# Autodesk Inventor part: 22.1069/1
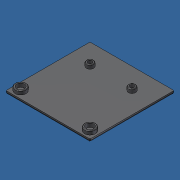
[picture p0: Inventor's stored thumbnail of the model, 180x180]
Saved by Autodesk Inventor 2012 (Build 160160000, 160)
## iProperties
Created: 2007-01
Part Number: 22.1069/1
Document SubType Name: Modeling
Designer: Andy Moles
Material: ABS Plastic
Density: 1.06 g/cm^3
Mass: 26.2439 g
Surface Area: 178.352 cm^2
Volume: 24.7584 cm^3
Description: END CAP 90X90 GRAY
Vendor: S
Author: Andy Moles
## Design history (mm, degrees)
sketch "Sketch1"
  geometry: L1 (-45, 45)-(45, 45); L2 (45, 45)-(45, -45); L3 (45, -45)-(-45, -45); L4 (-45, -45)-(-45, 45); 1 further point
  constraints: 8 end point, 2 parallel, 1 horizontal, 1 perpendicular
  dimensions: "WIDTH1" = 90 distance of L1.end L2.end; "WIDTH2" = 90 distance of L1.start L1.end; "d2" = 45 distance from line of point (0, 0) L1; "d3" = 45 distance from line of point (0, 0) L2
extrude "Extrusion1" new body sketch "Sketch1" distance "d4" = 3; taper "d5" = 0 deg
fillet "Fillet1" dims "d6" = 1
fillet "Fillet2" dims "d7" = 1.5
sketch "Sketch2"
  geometry: L1 (44, -45)-(-44, -45) reference; L2 (-44, 45)-(44, 45) reference; L3 (-45, -44)-(-45, 44) reference; C1 r 5.875 at (-37.15, -37.15); C2 r 4.25 at (-37.15, -37.15); C3 r 2.375 at (-22.5, 22.5); C4 r 3.825 at (-22.5, 22.5)
  constraints: 4 centre point, 2 coincident
  dimensions: "d8" = 8.5 diameter of C2; "d9" = 11.75 diameter of C1; "d10" = 4.75 diameter of C3; "d11" = 7.65 diameter of C4; "d12" = 7.85 distance from line of C1.centre L1; "d13" = 7.85 distance from line of C1.centre L3; "d14" = 22.5 distance from line of C3.centre L3; "d15" = 22.5 distance from line of C3.centre L2
extrude "Extrusion2" join sketch "Sketch2" distance "d16" = 4; taper "d17" = 0 deg
fillet "Fillet3" dims "d18" = 0.5
mirror "Mirror1"
body "Solid1"
